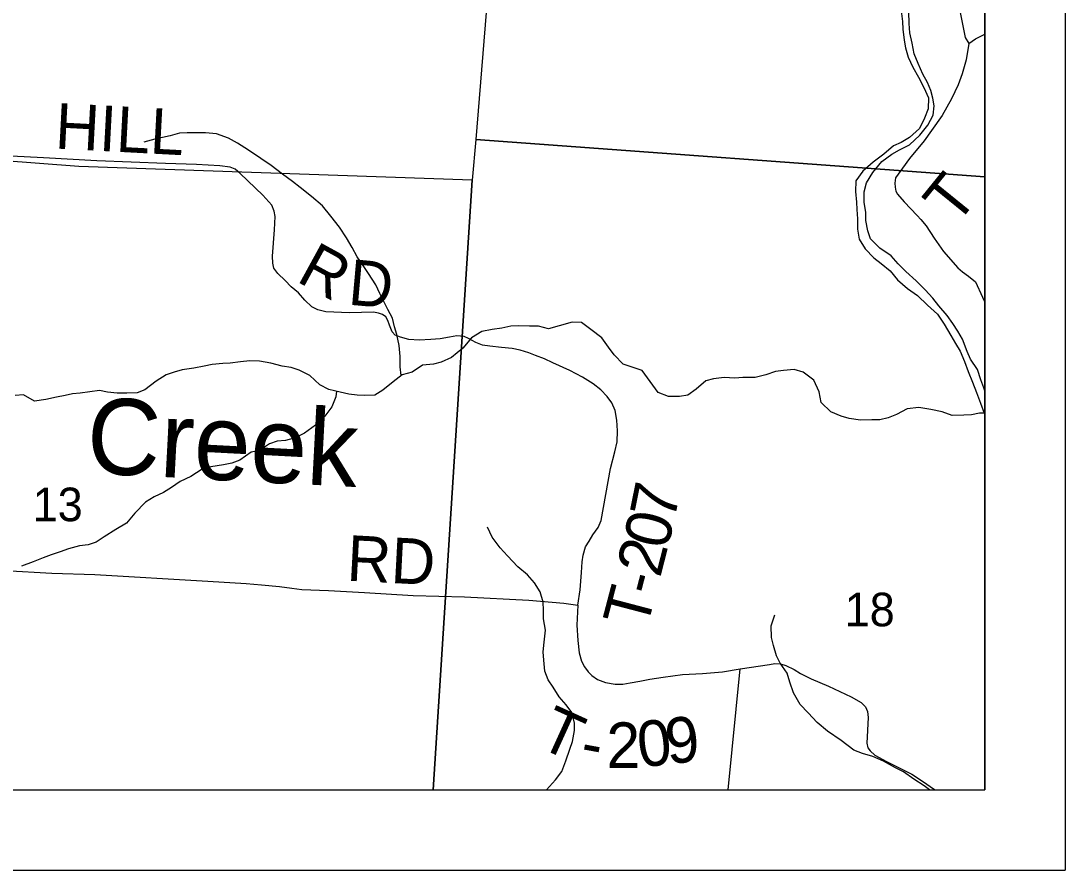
# Model space of a CAD drawing. Extents: x 0 to 40.8, y 0 to 22.
# Drawn here: x 7.699 to 9, y 14 to 15.058 of the extents above; entities that cross this region are included whole.
import ezdxf

# ---------------------------------------------------------------- set-up
doc = ezdxf.new("R2010")
doc.units = 0
for name, color, linetype in [('Default', 7, 'Continuous'), ('GM_X_County_Road', 7, 'Continuous'), ('GM_X_Major_River', 7, 'Continuous'), ('GM_X_Minor_River', 7, 'Continuous'), ('GM_X_Minor_River_Text', 7, 'Continuous'), ('GM_X_Section', 7, 'Continuous'), ('GM_X_Section_Text', 7, 'Continuous'), ('GM_X_Township_Road', 7, 'Continuous'), ('GM_X_Township_Road_Text', 7, 'Continuous'), ('SH_Cut_Line', 7, 'Continuous'), ('SH_Data', 7, 'Continuous')]:
    doc.layers.add(name, color=color, linetype=linetype)

msp = doc.modelspace()

# ---------------------------------------------------------------- linework, layer by layer
at = {"layer": 'Default'}
msp.add_lwpolyline([(2.1, 16.4387), (2.1, 14.1), (8.9, 14.1), (8.9, 16.9831), (7.7161, 17.0658), (7.7144, 17.066), (7.54, 17.0745), (7.4495, 17.0841), (6.9172, 17.1197), (6.1785, 17.166), (5.6278, 17.197), (5.3407, 17.2146), (4.8294, 17.2493), (4.5348, 17.2687), (3.4481, 17.3334), (3.1244, 17.3534), (2.8484, 17.3691), (2.8463, 17.3693), (2.4594, 17.3966), (2.4379, 17.0913), (2.3911, 16.4258)], close=True, dxfattribs=at)
at = {"layer": 'GM_X_County_Road'}
for points in [[(8.9, 14.8634), (8.9, 15.9059), (8.353, 15.9646), (8.344, 15.8695), (8.2661, 14.9102)], [(7.2324, 14.1), (8.213, 14.1), (8.2617, 14.8595), (7.7715, 14.8766), (7.2868, 14.9136)], [(8.213, 14.1), (8.9, 14.1), (8.9, 14.8634), (8.2661, 14.9102), (8.2617, 14.8595)]]:
    msp.add_lwpolyline(points, close=True, dxfattribs=at)
at = {"layer": 'GM_X_Major_River'}
for points in [[(8.7958, 15.0705), (8.7973, 15.0572), (8.798, 15.0477), (8.7996, 15.034), (8.8011, 15.0242), (8.8045, 15.0128), (8.8102, 15.0003), (8.8174, 14.9877), (8.8242, 14.9748), (8.8299, 14.9619), (8.8295, 14.9483), (8.8249, 14.9365), (8.8185, 14.9236), (8.806, 14.9126), (8.7957, 14.9062), (8.7863, 14.9024), (8.7741, 14.8918), (8.7609, 14.8819), (8.748, 14.8705), (8.7393, 14.8587), (8.7389, 14.8455), (8.74, 14.8322), (8.7404, 14.8227), (8.7415, 14.8113), (8.7415, 14.7984), (8.7434, 14.7859), (8.751, 14.7738), (8.7616, 14.7627), (8.7711, 14.7555), (8.7821, 14.7464), (8.7912, 14.7354), (8.8037, 14.7244), (8.8162, 14.7157), (8.8287, 14.7036), (8.8412, 14.6925), (8.8495, 14.68), (8.8578, 14.666), (8.8635, 14.6561), (8.8692, 14.6466), (8.8745, 14.6334), (8.8794, 14.6212), (8.8847, 14.6079), (8.8897, 14.595), (8.8946, 14.5817), (8.8991, 14.5692), (8.9, 14.5677)], [(8.9, 14.5972), (8.8986, 14.6006), (8.8949, 14.6108), (8.8907, 14.6237), (8.882, 14.6366), (8.8779, 14.6461), (8.8722, 14.6613), (8.8662, 14.6712), (8.8601, 14.6807), (8.8529, 14.6909), (8.8427, 14.7031), (8.8352, 14.7126), (8.8257, 14.7229), (8.8144, 14.7339), (8.8015, 14.7457), (8.7921, 14.7552), (8.7834, 14.765), (8.7694, 14.7749), (8.7576, 14.7863), (8.7542, 14.7962), (8.7516, 14.8091), (8.7516, 14.819), (8.7498, 14.8319), (8.7498, 14.8448), (8.7525, 14.8562), (8.7604, 14.8691), (8.7718, 14.8827), (8.7843, 14.8918), (8.7938, 14.8971), (8.806, 14.9035), (8.8189, 14.9156), (8.8291, 14.9278), (8.8356, 14.9403), (8.8371, 14.952), (8.8352, 14.9615), (8.8326, 14.971), (8.8288, 14.9813), (8.8228, 14.9915), (8.8171, 15.0048), (8.8118, 15.0169), (8.8096, 15.0299), (8.8066, 15.0431), (8.8058, 15.0545), (8.8055, 15.0693)]]:
    msp.add_lwpolyline(points, dxfattribs=at)
at = {"layer": 'GM_X_Minor_River'}
for points in [[(8.1731, 14.616), (8.172, 14.6268), (8.172, 14.6397), (8.1706, 14.6537), (8.1679, 14.667), (8.1649, 14.6769), (8.1623, 14.6875), (8.1566, 14.6985), (8.1517, 14.7084), (8.1464, 14.7183), (8.1415, 14.7289), (8.1324, 14.7433), (8.1256, 14.7532), (8.1181, 14.7638), (8.112, 14.7756), (8.1049, 14.7878), (8.0962, 14.8011), (8.0856, 14.8144), (8.075, 14.8273), (8.0614, 14.8391), (8.0474, 14.8505), (8.0376, 14.8577), (8.0251, 14.8668), (8.0111, 14.8779), (7.9982, 14.8866), (7.9831, 14.8969), (7.9691, 14.9056), (7.9581, 14.9117), (7.9433, 14.917), (7.9293, 14.9182), (7.9191, 14.9182), (7.9066, 14.9186), (7.8971, 14.9179), (7.8854, 14.9145), (7.8664, 14.9107), (7.8524, 14.9069)], [(8.8992, 14.569), (8.8933, 14.5691), (8.8834, 14.5672), (8.8739, 14.5668), (8.8592, 14.5661), (8.8467, 14.5707), (8.8327, 14.5737), (8.8179, 14.5764), (8.8031, 14.5745), (8.7898, 14.5677), (8.7796, 14.5632), (8.7694, 14.5609), (8.7591, 14.5609), (8.7451, 14.5606), (8.7311, 14.5625), (8.7209, 14.5656), (8.7084, 14.5709), (8.6963, 14.5823), (8.6937, 14.5956), (8.6869, 14.6104), (8.6736, 14.6203), (8.6626, 14.6237), (8.6494, 14.6222), (8.6395, 14.6211), (8.6274, 14.6169), (8.6141, 14.6135), (8.5986, 14.6136), (8.5887, 14.6128), (8.5755, 14.6136), (8.5622, 14.6121), (8.5527, 14.6095), (8.5406, 14.5992), (8.53, 14.5917), (8.5198, 14.5898), (8.5061, 14.5898), (8.4932, 14.5951), (8.4834, 14.6088), (8.4732, 14.6225), (8.4596, 14.6271), (8.4497, 14.6301), (8.4384, 14.6419), (8.4312, 14.6514), (8.4229, 14.6632), (8.4093, 14.6734), (8.3975, 14.6822), (8.3862, 14.6826), (8.3699, 14.6781), (8.3566, 14.6743), (8.3441, 14.6774), (8.3331, 14.6777), (8.3195, 14.6778), (8.3096, 14.6774), (8.2983, 14.6751), (8.2865, 14.6733), (8.2736, 14.671), (8.2607, 14.6631), (8.2497, 14.6502), (8.2357, 14.6384), (8.2228, 14.6328), (8.2133, 14.6301), (8.1997, 14.629), (8.1868, 14.6203), (8.1743, 14.6169), (8.1633, 14.6082), (8.1504, 14.598), (8.1401, 14.5915), (8.128, 14.5912), (8.1182, 14.5916), (8.1079, 14.5927), (8.097, 14.5954), (8.083, 14.5988), (8.072, 14.6046), (8.0595, 14.616), (8.0459, 14.6228), (8.036, 14.6259), (8.025, 14.6278), (8.0106, 14.6316), (7.9966, 14.6339), (7.9845, 14.6343), (7.9731, 14.6332), (7.9603, 14.6313), (7.9508, 14.6309), (7.9379, 14.6298), (7.9277, 14.6279), (7.9148, 14.6253), (7.9004, 14.623), (7.8905, 14.6204), (7.8803, 14.617), (7.8678, 14.6091), (7.8537, 14.5981), (7.8443, 14.5947), (7.8314, 14.5943), (7.8193, 14.594), (7.8075, 14.5955), (7.7973, 14.5974), (7.7734, 14.594), (7.7639, 14.5933), (7.7545, 14.5914), (7.7439, 14.5891), (7.7306, 14.5861), (7.7166, 14.5843)], [(8.0927, 14.5965), (8.0916, 14.5897), (8.0867, 14.5772), (8.078, 14.5655), (8.0662, 14.5541), (8.0529, 14.5443), (8.0397, 14.5382), (8.029, 14.5352), (8.0188, 14.5344), (8.009, 14.531), (7.9968, 14.5227), (7.9862, 14.5205), (7.9722, 14.5106), (7.9623, 14.5068), (7.9517, 14.505), (7.9362, 14.5023), (7.9252, 14.4993), (7.9111, 14.4902), (7.8979, 14.4842), (7.8872, 14.4766), (7.877, 14.4702), (7.8653, 14.4649), (7.8546, 14.4584), (7.8414, 14.4448), (7.8311, 14.4323), (7.8178, 14.4243), (7.8034, 14.4153), (7.7932, 14.4084), (7.7833, 14.405), (7.7723, 14.4039), (7.7587, 14.4002), (7.7485, 14.3964), (7.7371, 14.3926), (7.7272, 14.3888), (7.7147, 14.3839), (7.7003, 14.3786)], [(7.7166, 14.5843), (7.7026, 14.5919), (7.6923, 14.5911)], [(8.354, 14.1), (8.3541, 14.1002), (8.3655, 14.1123), (8.3731, 14.1229), (8.378, 14.1362), (8.383, 14.1506), (8.3864, 14.1601), (8.3891, 14.1741), (8.3891, 14.1836), (8.3857, 14.1965), (8.3785, 14.206), (8.3698, 14.2159), (8.3623, 14.2277), (8.3562, 14.2372), (8.3521, 14.2478), (8.3506, 14.2615), (8.3499, 14.2721), (8.351, 14.2838), (8.3529, 14.299), (8.3503, 14.3131), (8.3503, 14.3237), (8.35, 14.3336), (8.3462, 14.3465), (8.339, 14.3579), (8.3303, 14.3677), (8.3186, 14.3776), (8.3054, 14.3917), (8.2963, 14.4016), (8.2865, 14.4149), (8.2808, 14.4274)], [(8.831, 14.1), (8.8243, 14.1051), (8.8114, 14.1135), (8.7986, 14.1226), (8.7887, 14.1275), (8.7739, 14.1359), (8.7607, 14.1416), (8.7478, 14.1454), (8.7368, 14.1496), (8.721, 14.1614), (8.7039, 14.1732), (8.6914, 14.1839), (8.6801, 14.196), (8.6699, 14.2063), (8.6616, 14.2207), (8.657, 14.234), (8.654, 14.2454), (8.6453, 14.2576), (8.6404, 14.2671), (8.6367, 14.28), (8.6344, 14.2898), (8.6341, 14.3042), (8.6386, 14.3179)]]:
    msp.add_lwpolyline(points, dxfattribs=at)
at = {"layer": 'GM_X_Section'}
msp.add_lwpolyline([(8.344, 15.8695), (8.2661, 14.9102), (8.2617, 14.8595), (7.7715, 14.8766), (7.2868, 14.9136), (7.3612, 15.9396)], close=True, dxfattribs=at)
at = {"layer": 'GM_X_Township_Road'}
msp.add_line((8.5803, 14.1), (8.5953, 14.2506), dxfattribs=at)
for points in [[(8.8579, 15.1253), (8.8754, 15.0371), (8.8799, 15.0297)], [(8.8799, 15.0297), (8.8882, 15.0355), (8.9, 15.0414)], [(8.8799, 15.0297), (8.8766, 15.0093), (8.8716, 14.9918), (8.867, 14.9784), (8.8583, 14.9606), (8.847, 14.9402), (8.8335, 14.9214), (8.8246, 14.9086), (8.8063, 14.8866), (8.7889, 14.8622), (8.788, 14.8557), (8.7883, 14.8509), (8.7892, 14.8456), (8.7912, 14.842), (8.7994, 14.8323), (8.8159, 14.8155), (8.8203, 14.8105), (8.8271, 14.8026), (8.8369, 14.7872), (8.8486, 14.7705), (8.8663, 14.7504), (8.8721, 14.7453), (8.8795, 14.74), (8.8884, 14.7326), (8.8971, 14.7135), (8.9, 14.7073)], [(8.3931, 14.33), (8.3959, 14.3493), (8.3977, 14.3707), (8.3987, 14.3842), (8.3998, 14.3923), (8.4028, 14.4025), (8.4071, 14.4099), (8.4117, 14.4177), (8.4183, 14.4266), (8.4221, 14.4353), (8.4338, 14.5001), (8.4394, 14.521), (8.442, 14.5337), (8.4427, 14.5472), (8.4415, 14.5604), (8.4397, 14.5726), (8.4354, 14.582), (8.4298, 14.5899), (8.4216, 14.5981), (8.4122, 14.6059), (8.399, 14.6141), (8.383, 14.6225), (8.3619, 14.6321), (8.3514, 14.6367), (8.3405, 14.641), (8.3319, 14.6443), (8.3214, 14.6476), (8.3112, 14.6499), (8.298, 14.6512), (8.2835, 14.6525), (8.2744, 14.654), (8.2662, 14.6573), (8.2571, 14.6624), (8.2515, 14.6647), (8.2426, 14.6657), (8.2332, 14.6637), (8.2217, 14.6619), (8.21, 14.6609), (8.1955, 14.6601), (8.1826, 14.6611), (8.1724, 14.6637), (8.1658, 14.6662), (8.1617, 14.6705), (8.1584, 14.6787), (8.1566, 14.6845), (8.1538, 14.6894), (8.1498, 14.6922), (8.1447, 14.6939), (8.1388, 14.695), (8.1088, 14.6942), (8.0793, 14.6955), (8.0694, 14.698), (8.062, 14.7016), (8.0531, 14.71), (8.0452, 14.7191), (8.0363, 14.7267), (8.0287, 14.7346), (8.0193, 14.743), (8.0147, 14.7499), (8.0134, 14.756), (8.0129, 14.7646), (8.0155, 14.7974), (8.0162, 14.8142), (8.015, 14.8208), (8.0119, 14.8282), (8.0007, 14.8407), (7.9727, 14.8679), (7.9664, 14.873), (7.9603, 14.8755), (7.9473, 14.8773), (7.9183, 14.8791), (7.8794, 14.8804), (7.794, 14.8834), (7.7276, 14.8872), (7.6304, 14.8923)], [(7.6793, 14.3732), (7.738, 14.3699), (7.7914, 14.3684), (7.9323, 14.36), (7.9799, 14.3572), (7.9992, 14.3552), (8.0216, 14.3531), (8.0368, 14.3511), (8.0495, 14.3496), (8.0824, 14.3483), (8.1274, 14.3458), (8.1882, 14.3422), (8.252, 14.3404), (8.3321, 14.3364), (8.3756, 14.3325), (8.3931, 14.33)], [(8.3931, 14.33), (8.3919, 14.3053), (8.3931, 14.286), (8.3949, 14.2705), (8.3975, 14.2601), (8.4013, 14.2534), (8.4061, 14.2468), (8.4107, 14.2425), (8.4178, 14.2374), (8.4275, 14.2339), (8.4397, 14.2316), (8.4493, 14.2318), (8.4582, 14.2334), (8.4702, 14.2354), (8.4829, 14.2377), (8.4992, 14.2405), (8.5234, 14.2435), (8.5483, 14.2448), (8.5735, 14.2468), (8.5953, 14.2506), (8.632, 14.2562), (8.6386, 14.2573), (8.6454, 14.257), (8.652, 14.255), (8.6625, 14.2499), (8.6706, 14.2448), (8.6836, 14.2382), (8.7052, 14.2293), (8.7334, 14.2158), (8.7461, 14.2087), (8.7512, 14.2036), (8.7538, 14.1975), (8.7548, 14.1901), (8.753, 14.1583), (8.7545, 14.1522), (8.7571, 14.1484), (8.7629, 14.1431), (8.7774, 14.1354), (8.7932, 14.1276), (8.8092, 14.1194), (8.8222, 14.111), (8.8374, 14.1006), (8.8382, 14.1)]]:
    msp.add_lwpolyline(points, dxfattribs=at)
at = {"layer": 'SH_Cut_Line'}
msp.add_lwpolyline([(2.1, 17.4153), (2.1, 14.1), (8.9, 14.1), (8.9, 16.9831), (7.7161, 17.0658), (7.7144, 17.066), (7.54, 17.0745), (7.4495, 17.0841), (6.9172, 17.1197), (6.1785, 17.166), (5.6278, 17.197), (5.3407, 17.2146), (4.8294, 17.2493), (4.5348, 17.2687), (3.4481, 17.3334), (3.1244, 17.3534), (2.8484, 17.3691), (2.8463, 17.3693), (2.4594, 17.3966)], close=True, dxfattribs=at)
at = {"layer": 'SH_Data'}
for p, q in [((9, 21), (9, 14)), ((8.9, 20.9), (8.9, 14.1)), ((2.1, 14.1), (8.9, 14.1)), ((2, 14), (9, 14))]:
    msp.add_line(p, q, dxfattribs=at)

# ---------------------------------------------------------------- texts
at = {"layer": 'GM_X_Minor_River_Text'}
msp.add_text('Creek', height=0.09469, rotation=357.003, dxfattribs=at).set_placement((7.7797, 14.4948))
at = {"layer": 'GM_X_Section_Text'}
for s, p in [('13', (7.7142, 14.4346)), ('18', (8.7255, 14.3037))]:
    msp.add_text(s, height=0.04186, rotation=0, dxfattribs=at).set_placement(p)
at = {"layer": 'GM_X_Township_Road_Text'}
for s, height, rotation, p in [('HILL', 0.05682, 356.9878, (7.7412, 14.8989)), ('T', 0.0568, 50.9747, (8.8639, 14.8015)), ('R', 0.0568, 331.3173, (8.0411, 14.7342)), ('D', 0.0568, 354.948, (8.1059, 14.7045)), ('7', 0.0568, 78.5078, (8.5131, 14.434)), ('0', 0.0568, 76.4775, (8.5044, 14.3979)), ('RD', 0.05682, 357.0388, (8.1045, 14.3606)), ('2', 0.0568, 75.6379, (8.4955, 14.3631)), ('-', 0.0568, 75.3543, (8.4896, 14.3402)), ('T', 0.0568, 75.285, (8.4788, 14.299)), ('T', 0.0568, 335.5514, (8.3412, 14.1545)), ('9', 0.0568, 6.5922, (8.5053, 14.1317)), ('2', 0.0568, 0.3768, (8.4288, 14.1271)), ('0', 0.0568, 6.48, (8.4704, 14.1277)), ('-', 0.0568, 349.4323, (8.3941, 14.1324))]:
    msp.add_text(s, height=height, rotation=rotation, dxfattribs=at).set_placement(p)

doc.saveas('drawing.dxf')
